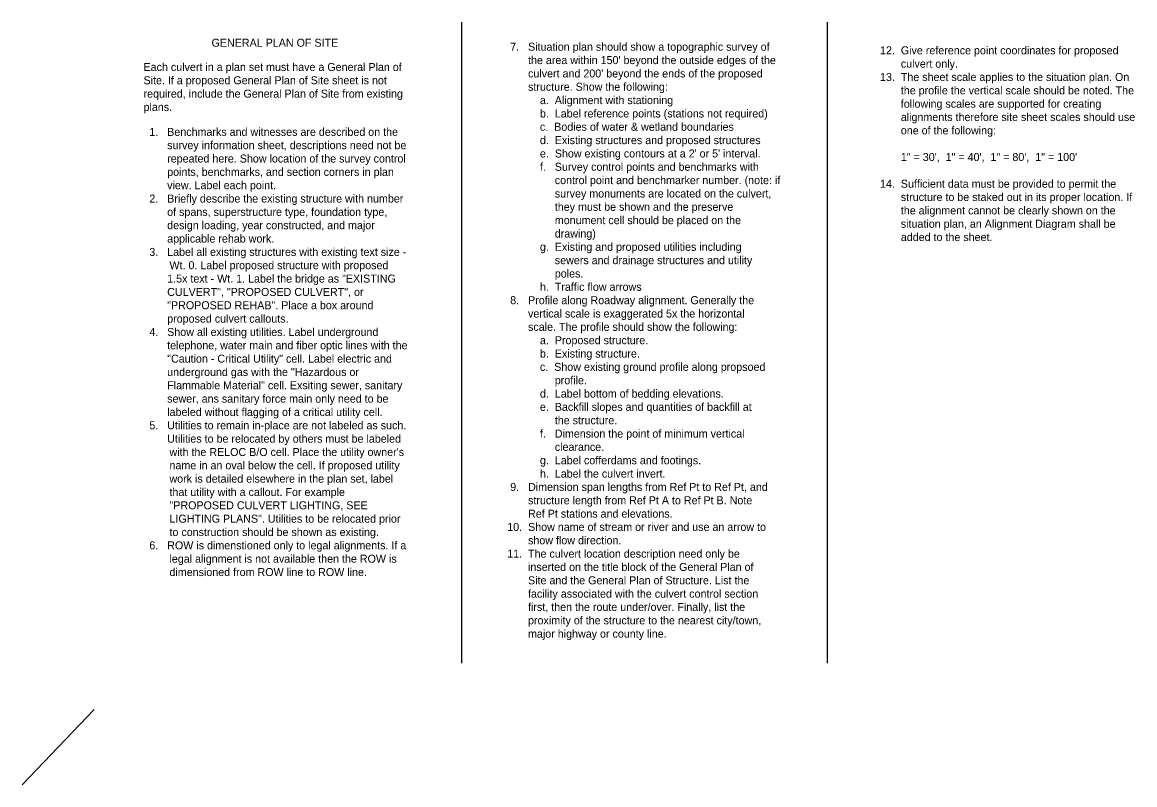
# Model space of a CAD drawing. Extents: x -2.03 to 1.46, y -0.09 to 0.96.
# Drawn here: x -2.035 to -0.644, y -0.094 to 0.859 of the extents above; entities that cross this region are included whole.
import ezdxf

# ---------------------------------------------------------------- set-up
doc = ezdxf.new("R2010")
doc.units = 0
doc.layers.add('Sheet_Label_Str_Wt0', color=7, linetype='Continuous')
doc.layers.add('Sheet_Label_Str_Wt2', color=7, linetype='Continuous')

msp = doc.modelspace()

# ---------------------------------------------------------------- linework, layer by layer
at = {"layer": 'Sheet_Label_Str_Wt0'}
for p, q in [((-1.4857, 0.8588), (-1.4857, 0.0579)), ((-1.0288, 0.8588), (-1.0288, 0.0579)), ((-1.9448, 0), (-2.0345, -0.0939))]:
    msp.add_line(p, q, dxfattribs=at)

# ---------------------------------------------------------------- texts
for s, p in [('GENERAL PLAN OF SITE', (-1.798, 0.8282)), ('    12.  Give reference point coordinates for proposed', (-0.9776, 0.8187)), ('           culvert only.', (-0.9776, 0.802)), ('    13.  The sheet scale applies to the situation plan. On', (-0.9776, 0.7854)), ('           the profile the vertical scale should be noted. The', (-0.9776, 0.7687)), ('           following scales are supported for creating', (-0.9776, 0.752)), ('           alignments therefore site sheet scales should use', (-0.9776, 0.7354)), ('           one of the following:', (-0.9776, 0.7187)), ('           1" = 30\',  1" = 40\',  1" = 80\',  1" = 100\'', (-0.9776, 0.6854)), ('    14.  Sufficient data must be provided to permit the', (-0.9776, 0.652)), ('           structure to be staked out in its proper location. If', (-0.9776, 0.6354)), ('           the alignment cannot be clearly shown on the', (-0.9776, 0.6187)), ('           situation plan, an Alignment Diagram shall be', (-0.9776, 0.602)), ('           added to the sheet.', (-0.9776, 0.5854))]:
    msp.add_text(s, height=0.01, dxfattribs=at).set_placement(p)
at = {"layer": 'Sheet_Label_Str_Wt2'}
for s, p in [('     7.   Situation plan should show a topographic survey of', (-1.4434, 0.8232)), ('Each culvert in a plan set must have a General Plan of', (-1.883, 0.7979)), ("           the area within 150' beyond the outside edges of the", (-1.4434, 0.8065)), ("           culvert and 200' beyond the ends of the proposed", (-1.4434, 0.7898)), ('Site. If a proposed General Plan of Site sheet is not', (-1.883, 0.7813)), ('           structure. Show the following:', (-1.4434, 0.7732)), ('required, include the General Plan of Site from existing', (-1.883, 0.7646)), ('               a.  Alignment with stationing', (-1.4434, 0.7565)), ('plans.', (-1.883, 0.7479)), ('               b.  Label reference points (stations not required)', (-1.4434, 0.7398)), ('     1.   Benchmarks and witnesses are described on the', (-1.8943, 0.7168)), ('               c.  Bodies of water & wetland boundaries', (-1.4434, 0.7232)), ('           survey information sheet, descriptions need not be', (-1.8943, 0.7002)), ('               d.  Existing structures and proposed structures', (-1.4434, 0.7065)), ("               e.  Show existing contours at a 2' or 5' interval.", (-1.4434, 0.6898)), ('           repeated here. Show location of the survey control', (-1.8943, 0.6835)), ('               f.   Survey control points and benchmarks with', (-1.4434, 0.6732)), ('           points, benchmarks, and section corners in plan', (-1.8943, 0.6668)), ('           view. Label each point.', (-1.8943, 0.6502)), ('                    control point and benchmarker number. (note: if', (-1.4434, 0.6565)), ('     2.   Briefly describe the existing structure with number', (-1.8943, 0.6335)), ('                    survey monuments are located on the culvert,', (-1.4434, 0.6398)), ('           of spans, superstructure type, foundation type,', (-1.8943, 0.6168)), ('                    they must be shown and the preserve', (-1.4434, 0.6232)), ('                    monument cell should be placed on the', (-1.4434, 0.6065)), ('           design loading, year constructed, and major', (-1.8943, 0.6002)), ('                    drawing)', (-1.4434, 0.5898)), ('           applicable rehab work.', (-1.8943, 0.5835)), ('     3.   Label all existing structures with existing text size - ', (-1.8943, 0.5668)), ('               g.  Existing and proposed utilities including', (-1.4434, 0.5732)), (' Wt. 0. Label proposed structure with proposed', (-1.8543, 0.5502)), ('                    sewers and drainage structures and utility', (-1.4434, 0.5565)), ('           1.5x text - Wt. 1. Label the bridge as "EXISTING', (-1.8943, 0.5335)), ('                    poles.', (-1.4434, 0.5398)), ('               h.  Traffic flow arrows', (-1.4434, 0.5232)), ('           CULVERT", "PROPOSED CULVERT", or', (-1.8943, 0.5168)), ('     8.   Profile along Roadway alignment. Generally the', (-1.4434, 0.5065)), ('           "PROPOSED REHAB". Place a box around', (-1.8943, 0.5002)), ('           proposed culvert callouts.', (-1.8943, 0.4835)), ('           vertical scale is exaggerated 5x the horizontal', (-1.4434, 0.4898)), ('     4.   Show all existing utilities. Label underground', (-1.8943, 0.4668)), ('           scale. The profile should show the following:', (-1.4434, 0.4732)), ('           telephone, water main and fiber optic lines with the ', (-1.8943, 0.4502)), ('               a.  Proposed structure.', (-1.4434, 0.4565)), ('               b.  Existing structure.', (-1.4434, 0.4398)), ('           "Caution - Critical Utility" cell. Label electric and', (-1.8943, 0.4335)), ('               c.  Show existing ground profile along propsoed', (-1.4434, 0.4232)), ('           underground gas with the "Hazardous or', (-1.8943, 0.4168)), ('           Flammable Material" cell. Exsiting sewer, sanitary', (-1.8943, 0.4002)), ('                    profile.', (-1.4434, 0.4065)), ('           sewer, ans sanitary force main only need to be', (-1.8943, 0.3835)), ('               d.  Label bottom of bedding elevations.', (-1.4434, 0.3898)), ('           labeled without flagging of a critical utility cell.', (-1.8943, 0.3668)), ('               e.  Backfill slopes and quantities of backfill at', (-1.4434, 0.3732)), ('                    the structure.', (-1.4434, 0.3565)), ('     5.   Utilities to remain in-place are not labeled as such.', (-1.8943, 0.3502)), ('               f.   Dimension the point of minimum vertical', (-1.4434, 0.3398)), ('           Utilities to be relocated by others must be labeled', (-1.8943, 0.3335)), ('                    clearance.', (-1.4434, 0.3232)), (" with the RELOC B/O cell. Place the utility owner's", (-1.8543, 0.3168)), (' name in an oval below the cell. If proposed utility', (-1.8543, 0.3002)), ('               g.  Label cofferdams and footings.', (-1.4434, 0.3065)), (' work is detailed elsewhere in the plan set, label', (-1.8543, 0.2835)), ('               h.  Label the culvert invert.', (-1.4434, 0.2898)), ('     9.   Dimension span lengths from Ref Pt to Ref Pt, and', (-1.4434, 0.2732)), (' that utility with a callout. For example', (-1.8543, 0.2668)), ('           structure length from Ref Pt A to Ref Pt B. Note', (-1.4434, 0.2565)), (' "PROPOSED CULVERT LIGHTING, SEE', (-1.8543, 0.2502)), ('           Ref Pt stations and elevations.', (-1.4434, 0.2398)), (' LIGHTING PLANS". Utilities to be relocated prior', (-1.8543, 0.2335)), (' to construction should be shown as existing.', (-1.8543, 0.2168)), ('    10.  Show name of stream or river and use an arrow to', (-1.4434, 0.2232)), ('     6.   ROW is dimenstioned only to legal alignments. If a', (-1.8943, 0.2002)), ('           show flow direction.', (-1.4434, 0.2065)), ('    11.  The culvert location description need only be', (-1.4434, 0.1898)), (' legal alignment is not available then the ROW is', (-1.8543, 0.1835)), ('           inserted on the title block of the General Plan of', (-1.4434, 0.1732)), (' dimensioned from ROW line to ROW line.', (-1.8543, 0.1668)), ('           Site and the General Plan of Structure. List the', (-1.4434, 0.1565)), ('           facility associated with the culvert control section', (-1.4434, 0.1398)), ('           first, then the route under/over. Finally, list the', (-1.4434, 0.1232)), ('           proximity of the structure to the nearest city/town,', (-1.4434, 0.1065)), ('           major highway or county line.', (-1.4434, 0.0898))]:
    msp.add_text(s, height=0.01, dxfattribs=at).set_placement(p)

doc.saveas('drawing.dxf')
